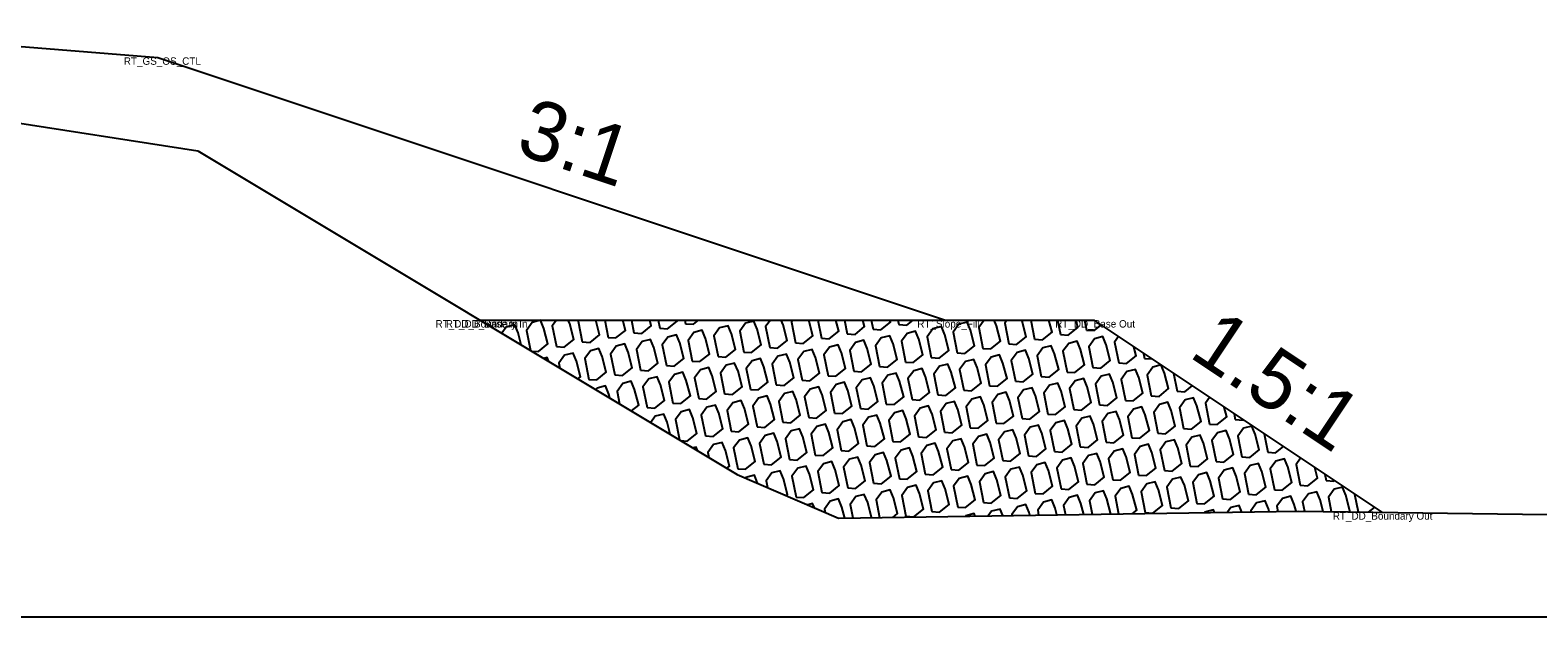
# Model space of a CAD drawing. Extents: x -26 to 203, y -10 to 20020.
# Drawn here: x 118.28 to 138.62, y 15500 to 15507.91 of the extents above; entities that cross this region are included whole.
import ezdxf

# ---------------------------------------------------------------- set-up
doc = ezdxf.new("R2010")
doc.units = 0
for name, color, linetype in [('Default', 7, 'Continuous'), ('Exist Cross Section Cell', 7, 'Continuous'), ('Exist XS Ground Line', 7, 'Continuous'), ('Old_Level_1', 7, 'Continuous'), ('Prop CMT Rip Rap Class II', 7, 'Continuous'), ('Prop CMT Slope Grass', 7, 'Continuous'), ('Prop XS Side Slope Text', 7, 'Continuous')]:
    doc.layers.add(name, color=color, linetype=linetype)

msp = doc.modelspace()

# ---------------------------------------------------------------- linework, layer by layer
at = {"layer": 'Exist Cross Section Cell'}
msp.add_line((100, 15500), (200, 15500), dxfattribs=at)
at = {"layer": 'Exist XS Ground Line'}
for p, q in [((116.112, 15506.968), (120.537, 15506.282)), ((120.537, 15506.282), (127.816, 15501.92)), ((127.816, 15501.92), (129.182, 15501.33)), ((129.182, 15501.33), (135.384, 15501.425)), ((135.384, 15501.425), (151.355, 15501.217))]:
    msp.add_line(p, q, dxfattribs=at)
at = {"layer": 'Old_Level_1'}
for p, q in [((124.378, 15503.98), (124.403, 15504)), ((126.028, 15504), (126.074, 15503.767)), ((126.389, 15504), (126.423, 15503.828)), ((126.749, 15504), (126.771, 15503.89)), ((127.11, 15504), (127.12, 15503.951)), ((128.903, 15504), (128.952, 15503.755)), ((129.264, 15504), (129.3, 15503.816)), ((129.625, 15504), (129.649, 15503.877)), ((129.985, 15504), (129.998, 15503.939)), ((131.778, 15504), (131.829, 15503.742)), ((132.139, 15504), (132.178, 15503.804)), ((132.5, 15504), (132.527, 15503.865)), ((133.299, 15503.552), (133.313, 15503.484)), ((133.313, 15503.484), (133.412, 15503.477)), ((133.702, 15503.283), (133.75, 15503.041)), ((134.521, 15502.737), (134.536, 15502.66)), ((134.924, 15502.469), (134.974, 15502.218)), ((135.743, 15501.923), (135.76, 15501.837)), ((136.146, 15501.654), (136.193, 15501.414)), ((136.335, 15501.412), (136.414, 15501.475))]:
    msp.add_line(p, q, dxfattribs=at)
for points in [[(125.044, 15503.581), (125.134, 15503.575), (125.263, 15503.678), (125.209, 15503.889), (125.164, 15503.998), (125.05, 15503.969), (124.973, 15503.862), (125.026, 15503.592)], [(125.376, 15504), (125.321, 15503.924), (125.377, 15503.644)], [(125.377, 15503.644), (125.482, 15503.636), (125.612, 15503.74), (125.557, 15503.95), (125.537, 15504)], [(125.68, 15504), (125.67, 15503.985), (125.725, 15503.705)], [(125.725, 15503.705), (125.831, 15503.698), (125.96, 15503.801), (125.909, 15504)], [(126.074, 15503.767), (126.179, 15503.759), (126.309, 15503.862), (126.273, 15504)], [(126.423, 15503.828), (126.528, 15503.821), (126.657, 15503.924), (126.638, 15504)], [(126.771, 15503.89), (126.877, 15503.882), (127.006, 15503.985), (127.002, 15504)], [(127.12, 15503.951), (127.225, 15503.944), (127.296, 15504)], [(128.263, 15504), (128.199, 15503.912), (128.255, 15503.632)], [(128.255, 15503.632), (128.36, 15503.624), (128.489, 15503.727), (128.435, 15503.938), (128.409, 15504)], [(128.567, 15504), (128.548, 15503.973), (128.603, 15503.693)], [(128.603, 15503.693), (128.708, 15503.685), (128.838, 15503.789), (128.784, 15503.999), (128.783, 15504)], [(128.952, 15503.755), (129.057, 15503.747), (129.187, 15503.85), (129.148, 15504)], [(129.3, 15503.816), (129.406, 15503.808), (129.535, 15503.912), (129.512, 15504)], [(129.649, 15503.877), (129.754, 15503.87), (129.884, 15503.973), (129.877, 15504)], [(129.998, 15503.939), (130.103, 15503.931), (130.189, 15504)], [(130.352, 15504), (130.451, 15503.993), (130.46, 15504)], [(131.15, 15504), (131.077, 15503.899), (131.132, 15503.619)], [(131.132, 15503.619), (131.237, 15503.612), (131.367, 15503.715), (131.313, 15503.925), (131.282, 15504)], [(131.454, 15504), (131.425, 15503.961), (131.481, 15503.681)], [(131.481, 15503.681), (131.586, 15503.673), (131.716, 15503.776), (131.661, 15503.987), (131.656, 15504)], [(131.829, 15503.742), (131.935, 15503.735), (132.064, 15503.838), (132.022, 15504)], [(132.178, 15503.804), (132.283, 15503.796), (132.413, 15503.899), (132.387, 15504)], [(124.902, 15503.667), (124.86, 15503.827), (124.815, 15503.937), (124.701, 15503.907), (124.64, 15503.823)], [(132.527, 15503.865), (132.632, 15503.858), (132.727, 15503.933)], [(132.962, 15503.777), (132.908, 15503.703), (132.964, 15503.423)], [(125.667, 15503.208), (125.701, 15503.235), (125.646, 15503.446), (125.601, 15503.556), (125.487, 15503.526), (125.41, 15503.42), (125.423, 15503.354)], [(132.964, 15503.423), (133.069, 15503.415), (133.199, 15503.518), (133.167, 15503.64)], [(125.273, 15503.444), (125.252, 15503.494), (125.208, 15503.483)], [(133.534, 15503.395), (133.423, 15503.366), (133.346, 15503.26), (133.402, 15502.98)], [(133.402, 15502.98), (133.507, 15502.972), (133.636, 15503.076), (133.582, 15503.286), (133.538, 15503.393)], [(126.388, 15502.776), (126.487, 15502.854), (126.432, 15503.065), (126.387, 15503.175), (126.273, 15503.145), (126.196, 15503.039), (126.23, 15502.871)], [(126.097, 15502.95), (126.084, 15503.003), (126.038, 15503.113), (125.925, 15503.084), (125.91, 15503.063)], [(133.75, 15503.041), (133.855, 15503.034), (133.956, 15503.114)], [(133.839, 15502.537), (133.944, 15502.53), (134.074, 15502.633), (134.019, 15502.843), (133.974, 15502.953), (133.86, 15502.924), (133.783, 15502.817), (133.839, 15502.537)], [(134.19, 15502.958), (134.132, 15502.879), (134.188, 15502.599)], [(126.911, 15502.463), (126.87, 15502.622), (126.825, 15502.732), (126.711, 15502.703), (126.65, 15502.619)], [(127.055, 15502.376), (127.143, 15502.37), (127.273, 15502.473), (127.218, 15502.684), (127.173, 15502.793), (127.059, 15502.764), (126.982, 15502.658), (127.036, 15502.388)], [(134.188, 15502.599), (134.293, 15502.591), (134.422, 15502.694), (134.388, 15502.826)], [(134.536, 15502.66), (134.641, 15502.653), (134.644, 15502.655)], [(127.677, 15502.004), (127.71, 15502.031), (127.656, 15502.241), (127.611, 15502.351), (127.497, 15502.321), (127.42, 15502.215), (127.433, 15502.15)], [(134.277, 15502.095), (134.382, 15502.087), (134.511, 15502.19), (134.457, 15502.401), (134.412, 15502.511), (134.298, 15502.481), (134.221, 15502.375), (134.277, 15502.095)], [(127.282, 15502.24), (127.262, 15502.289), (127.219, 15502.278)], [(134.974, 15502.218), (135.079, 15502.21), (135.185, 15502.295)], [(135.063, 15501.714), (135.168, 15501.706), (135.297, 15501.809), (135.243, 15502.02), (135.198, 15502.129), (135.084, 15502.1), (135.007, 15501.994), (135.063, 15501.714)], [(135.417, 15502.14), (135.356, 15502.055), (135.411, 15501.775)], [(128.092, 15501.801), (128.048, 15501.908), (127.934, 15501.879), (127.929, 15501.871)], [(128.478, 15501.635), (128.496, 15501.649), (128.442, 15501.86), (128.397, 15501.97), (128.283, 15501.94), (128.206, 15501.834), (128.224, 15501.744)], [(134.714, 15501.652), (134.819, 15501.645), (134.949, 15501.748), (134.894, 15501.958), (134.849, 15502.068), (134.735, 15502.039), (134.658, 15501.932), (134.714, 15501.652)], [(135.411, 15501.775), (135.516, 15501.767), (135.646, 15501.871), (135.61, 15502.012)], [(129.917, 15501.341), (129.98, 15501.391), (129.925, 15501.602), (129.88, 15501.712), (129.766, 15501.682), (129.689, 15501.576), (129.736, 15501.339)], [(130.093, 15501.357), (130.199, 15501.35), (130.328, 15501.453), (130.274, 15501.663), (130.229, 15501.773), (130.115, 15501.744), (130.038, 15501.637), (130.093, 15501.357)], [(130.442, 15501.419), (130.547, 15501.411), (130.677, 15501.514), (130.622, 15501.725), (130.577, 15501.834), (130.463, 15501.805), (130.386, 15501.699), (130.442, 15501.419)], [(130.791, 15501.48), (130.896, 15501.472), (131.025, 15501.576), (130.971, 15501.786), (130.926, 15501.896), (130.812, 15501.867), (130.735, 15501.76), (130.791, 15501.48)], [(133.143, 15501.39), (133.206, 15501.44), (133.151, 15501.651), (133.106, 15501.761), (132.992, 15501.731), (132.915, 15501.625), (132.962, 15501.388)], [(133.32, 15501.406), (133.425, 15501.399), (133.554, 15501.502), (133.5, 15501.712), (133.455, 15501.822), (133.341, 15501.793), (133.264, 15501.686), (133.32, 15501.406)], [(135.76, 15501.837), (135.865, 15501.829), (135.873, 15501.836)], [(136.068, 15501.416), (136.083, 15501.428), (136.029, 15501.639), (135.984, 15501.748), (135.87, 15501.719), (135.793, 15501.612), (135.831, 15501.419)], [(128.858, 15501.47), (128.834, 15501.527), (128.767, 15501.51)], [(129.266, 15501.331), (129.228, 15501.479), (129.183, 15501.589), (129.069, 15501.559), (128.992, 15501.453), (129.001, 15501.408)], [(129.629, 15501.337), (129.577, 15501.54), (129.531, 15501.65), (129.418, 15501.621), (129.341, 15501.514), (129.377, 15501.333)], [(131.766, 15501.369), (131.757, 15501.405), (131.712, 15501.515), (131.598, 15501.485), (131.521, 15501.379), (131.524, 15501.366)], [(132.129, 15501.375), (132.106, 15501.467), (132.06, 15501.576), (131.947, 15501.547), (131.87, 15501.44), (131.883, 15501.371)], [(132.492, 15501.381), (132.454, 15501.528), (132.409, 15501.638), (132.295, 15501.608), (132.218, 15501.502), (132.243, 15501.377)], [(132.855, 15501.386), (132.803, 15501.589), (132.758, 15501.699), (132.644, 15501.67), (132.567, 15501.563), (132.603, 15501.382)], [(134.626, 15501.413), (134.589, 15501.502), (134.476, 15501.473), (134.43, 15501.41)], [(134.992, 15501.419), (134.983, 15501.454), (134.938, 15501.564), (134.824, 15501.535), (134.747, 15501.428), (134.75, 15501.415)], [(135.355, 15501.424), (135.332, 15501.516), (135.287, 15501.625), (135.173, 15501.596), (135.096, 15501.49), (135.11, 15501.42)], [(135.721, 15501.42), (135.68, 15501.577), (135.635, 15501.687), (135.522, 15501.657), (135.444, 15501.551), (135.47, 15501.424)], [(131.028, 15501.358), (131.015, 15501.392), (130.901, 15501.362), (130.896, 15501.356)], [(131.4, 15501.364), (131.363, 15501.453), (131.249, 15501.424), (131.204, 15501.361)], [(134.255, 15501.407), (134.241, 15501.441), (134.127, 15501.412), (134.123, 15501.405)]]:
    msp.add_lwpolyline(points, dxfattribs=at)
for points in [[(127.906, 15503.57), (128.011, 15503.563), (128.141, 15503.666), (128.086, 15503.876), (128.041, 15503.986), (127.927, 15503.957), (127.85, 15503.85)], [(130.784, 15503.558), (130.889, 15503.55), (131.018, 15503.653), (130.964, 15503.864), (130.919, 15503.974), (130.805, 15503.944), (130.728, 15503.838)], [(126.512, 15503.324), (126.617, 15503.317), (126.746, 15503.42), (126.692, 15503.63), (126.647, 15503.74), (126.533, 15503.711), (126.456, 15503.604)], [(126.86, 15503.386), (126.965, 15503.378), (127.095, 15503.481), (127.041, 15503.692), (126.995, 15503.802), (126.882, 15503.772), (126.805, 15503.666)], [(127.209, 15503.447), (127.314, 15503.44), (127.444, 15503.543), (127.389, 15503.753), (127.344, 15503.863), (127.23, 15503.834), (127.153, 15503.727)], [(127.557, 15503.509), (127.663, 15503.501), (127.792, 15503.604), (127.738, 15503.815), (127.693, 15503.925), (127.579, 15503.895), (127.502, 15503.789)], [(129.738, 15503.373), (129.843, 15503.366), (129.973, 15503.469), (129.918, 15503.68), (129.873, 15503.789), (129.759, 15503.76), (129.682, 15503.653)], [(130.086, 15503.435), (130.192, 15503.427), (130.321, 15503.53), (130.267, 15503.741), (130.222, 15503.851), (130.108, 15503.821), (130.031, 15503.715)], [(130.435, 15503.496), (130.54, 15503.489), (130.67, 15503.592), (130.615, 15503.803), (130.57, 15503.912), (130.456, 15503.883), (130.379, 15503.776)], [(132.615, 15503.361), (132.721, 15503.353), (132.85, 15503.457), (132.796, 15503.667), (132.751, 15503.777), (132.637, 15503.748), (132.56, 15503.641)], [(125.814, 15503.201), (125.92, 15503.194), (126.049, 15503.297), (125.995, 15503.508), (125.95, 15503.617), (125.836, 15503.588), (125.759, 15503.481)], [(126.163, 15503.263), (126.268, 15503.255), (126.398, 15503.358), (126.343, 15503.569), (126.298, 15503.679), (126.184, 15503.649), (126.107, 15503.543)], [(128.343, 15503.128), (128.449, 15503.12), (128.578, 15503.223), (128.524, 15503.434), (128.479, 15503.543), (128.365, 15503.514), (128.288, 15503.408)], [(128.692, 15503.189), (128.797, 15503.181), (128.927, 15503.285), (128.872, 15503.495), (128.827, 15503.605), (128.713, 15503.575), (128.636, 15503.469)], [(129.041, 15503.25), (129.146, 15503.243), (129.275, 15503.346), (129.221, 15503.557), (129.176, 15503.666), (129.062, 15503.637), (128.985, 15503.53)], [(129.389, 15503.312), (129.494, 15503.304), (129.624, 15503.408), (129.57, 15503.618), (129.524, 15503.728), (129.411, 15503.698), (129.334, 15503.592)], [(131.57, 15503.177), (131.675, 15503.169), (131.804, 15503.272), (131.75, 15503.483), (131.705, 15503.593), (131.591, 15503.563), (131.514, 15503.457)], [(131.918, 15503.238), (132.024, 15503.231), (132.153, 15503.334), (132.099, 15503.544), (132.053, 15503.654), (131.94, 15503.625), (131.863, 15503.518)], [(132.267, 15503.3), (132.372, 15503.292), (132.502, 15503.395), (132.447, 15503.606), (132.402, 15503.715), (132.288, 15503.686), (132.211, 15503.58)], [(127.298, 15502.943), (127.403, 15502.936), (127.532, 15503.039), (127.478, 15503.249), (127.433, 15503.359), (127.319, 15503.33), (127.242, 15503.223)], [(127.646, 15503.005), (127.752, 15502.997), (127.881, 15503.1), (127.827, 15503.311), (127.781, 15503.42), (127.668, 15503.391), (127.591, 15503.285)], [(127.995, 15503.066), (128.1, 15503.058), (128.23, 15503.162), (128.175, 15503.372), (128.13, 15503.482), (128.016, 15503.453), (127.939, 15503.346)], [(130.175, 15502.931), (130.281, 15502.923), (130.41, 15503.026), (130.356, 15503.237), (130.311, 15503.347), (130.197, 15503.317), (130.12, 15503.211)], [(130.524, 15502.992), (130.629, 15502.985), (130.759, 15503.088), (130.704, 15503.298), (130.659, 15503.408), (130.545, 15503.379), (130.468, 15503.272)], [(130.872, 15503.054), (130.978, 15503.046), (131.107, 15503.149), (131.053, 15503.36), (131.008, 15503.47), (130.894, 15503.44), (130.817, 15503.334)], [(131.221, 15503.115), (131.326, 15503.108), (131.456, 15503.211), (131.401, 15503.421), (131.356, 15503.531), (131.243, 15503.502), (131.165, 15503.395)], [(133.053, 15502.918), (133.158, 15502.911), (133.288, 15503.014), (133.233, 15503.225), (133.188, 15503.334), (133.074, 15503.305), (132.997, 15503.198)], [(126.6, 15502.82), (126.706, 15502.813), (126.835, 15502.916), (126.781, 15503.126), (126.736, 15503.236), (126.622, 15503.207), (126.545, 15503.1)], [(126.949, 15502.882), (127.054, 15502.874), (127.184, 15502.977), (127.129, 15503.188), (127.084, 15503.298), (126.971, 15503.268), (126.893, 15503.162)], [(129.13, 15502.746), (129.235, 15502.739), (129.364, 15502.842), (129.31, 15503.053), (129.265, 15503.162), (129.151, 15503.133), (129.074, 15503.026)], [(129.478, 15502.808), (129.583, 15502.8), (129.713, 15502.903), (129.658, 15503.114), (129.613, 15503.224), (129.5, 15503.194), (129.422, 15503.088)], [(129.827, 15502.869), (129.932, 15502.862), (130.062, 15502.965), (130.007, 15503.176), (129.962, 15503.285), (129.848, 15503.256), (129.771, 15503.149)], [(132.007, 15502.734), (132.112, 15502.726), (132.242, 15502.83), (132.188, 15503.04), (132.142, 15503.15), (132.029, 15503.121), (131.952, 15503.014)], [(132.356, 15502.796), (132.461, 15502.788), (132.591, 15502.891), (132.536, 15503.102), (132.491, 15503.211), (132.377, 15503.182), (132.3, 15503.076)], [(132.704, 15502.857), (132.81, 15502.849), (132.939, 15502.953), (132.885, 15503.163), (132.84, 15503.273), (132.726, 15503.243), (132.649, 15503.137)], [(128.084, 15502.562), (128.189, 15502.554), (128.319, 15502.658), (128.264, 15502.868), (128.219, 15502.978), (128.105, 15502.948), (128.028, 15502.842)], [(128.432, 15502.623), (128.538, 15502.616), (128.667, 15502.719), (128.613, 15502.93), (128.568, 15503.039), (128.454, 15503.01), (128.377, 15502.903)], [(128.781, 15502.685), (128.886, 15502.677), (129.016, 15502.781), (128.961, 15502.991), (128.916, 15503.101), (128.802, 15503.071), (128.725, 15502.965)], [(130.961, 15502.55), (131.067, 15502.542), (131.196, 15502.645), (131.142, 15502.856), (131.097, 15502.966), (130.983, 15502.936), (130.906, 15502.83)], [(131.31, 15502.611), (131.415, 15502.604), (131.545, 15502.707), (131.49, 15502.917), (131.445, 15503.027), (131.331, 15502.998), (131.254, 15502.891)], [(131.659, 15502.673), (131.764, 15502.665), (131.893, 15502.768), (131.839, 15502.979), (131.794, 15503.088), (131.68, 15503.059), (131.603, 15502.953)], [(127.387, 15502.439), (127.492, 15502.431), (127.621, 15502.535), (127.567, 15502.745), (127.522, 15502.855), (127.408, 15502.826), (127.331, 15502.719)], [(127.735, 15502.501), (127.84, 15502.493), (127.97, 15502.596), (127.915, 15502.807), (127.87, 15502.916), (127.757, 15502.887), (127.68, 15502.781)], [(129.567, 15502.304), (129.672, 15502.296), (129.802, 15502.399), (129.747, 15502.61), (129.702, 15502.72), (129.588, 15502.69), (129.511, 15502.584)], [(129.916, 15502.365), (130.021, 15502.358), (130.15, 15502.461), (130.096, 15502.671), (130.051, 15502.781), (129.937, 15502.752), (129.86, 15502.645)], [(130.264, 15502.427), (130.369, 15502.419), (130.499, 15502.522), (130.445, 15502.733), (130.399, 15502.843), (130.286, 15502.813), (130.209, 15502.707)], [(130.613, 15502.488), (130.718, 15502.481), (130.848, 15502.584), (130.793, 15502.794), (130.748, 15502.904), (130.634, 15502.875), (130.557, 15502.768)], [(132.793, 15502.353), (132.899, 15502.345), (133.028, 15502.449), (132.974, 15502.659), (132.928, 15502.769), (132.815, 15502.739), (132.738, 15502.633)], [(133.142, 15502.414), (133.247, 15502.407), (133.377, 15502.51), (133.322, 15502.721), (133.277, 15502.83), (133.163, 15502.801), (133.086, 15502.694)], [(133.49, 15502.476), (133.596, 15502.468), (133.725, 15502.571), (133.671, 15502.782), (133.626, 15502.892), (133.512, 15502.862), (133.435, 15502.756)], [(128.521, 15502.119), (128.626, 15502.112), (128.756, 15502.215), (128.702, 15502.426), (128.656, 15502.535), (128.543, 15502.506), (128.466, 15502.399)], [(128.87, 15502.181), (128.975, 15502.173), (129.105, 15502.276), (129.05, 15502.487), (129.005, 15502.597), (128.891, 15502.567), (128.814, 15502.461)], [(129.218, 15502.242), (129.324, 15502.235), (129.453, 15502.338), (129.399, 15502.548), (129.354, 15502.658), (129.24, 15502.629), (129.163, 15502.522)], [(131.399, 15502.107), (131.504, 15502.099), (131.634, 15502.203), (131.579, 15502.413), (131.534, 15502.523), (131.42, 15502.494), (131.343, 15502.387)], [(131.747, 15502.169), (131.853, 15502.161), (131.982, 15502.264), (131.928, 15502.475), (131.883, 15502.584), (131.769, 15502.555), (131.692, 15502.449)], [(132.096, 15502.23), (132.201, 15502.222), (132.331, 15502.326), (132.276, 15502.536), (132.231, 15502.646), (132.117, 15502.616), (132.04, 15502.51)], [(132.445, 15502.291), (132.55, 15502.284), (132.679, 15502.387), (132.625, 15502.598), (132.58, 15502.707), (132.466, 15502.678), (132.389, 15502.571)], [(134.625, 15502.156), (134.73, 15502.149), (134.86, 15502.252), (134.805, 15502.462), (134.76, 15502.572), (134.647, 15502.543), (134.569, 15502.436)], [(127.824, 15501.996), (127.929, 15501.989), (128.059, 15502.092), (128.004, 15502.303), (127.959, 15502.412), (127.845, 15502.383), (127.768, 15502.276)], [(128.173, 15502.058), (128.278, 15502.05), (128.407, 15502.154), (128.353, 15502.364), (128.308, 15502.474), (128.194, 15502.444), (128.117, 15502.338)], [(130.353, 15501.923), (130.458, 15501.915), (130.588, 15502.018), (130.533, 15502.229), (130.488, 15502.339), (130.375, 15502.309), (130.297, 15502.203)], [(130.702, 15501.984), (130.807, 15501.977), (130.936, 15502.08), (130.882, 15502.29), (130.837, 15502.4), (130.723, 15502.371), (130.646, 15502.264)], [(131.05, 15502.046), (131.156, 15502.038), (131.285, 15502.141), (131.231, 15502.352), (131.185, 15502.461), (131.072, 15502.432), (130.995, 15502.326)], [(133.231, 15501.91), (133.336, 15501.903), (133.466, 15502.006), (133.411, 15502.216), (133.366, 15502.326), (133.252, 15502.297), (133.175, 15502.19)], [(133.579, 15501.972), (133.685, 15501.964), (133.814, 15502.067), (133.76, 15502.278), (133.715, 15502.388), (133.601, 15502.358), (133.524, 15502.252)], [(133.928, 15502.033), (134.033, 15502.026), (134.163, 15502.129), (134.108, 15502.339), (134.063, 15502.449), (133.949, 15502.42), (133.872, 15502.313)], [(129.307, 15501.738), (129.413, 15501.731), (129.542, 15501.834), (129.488, 15502.044), (129.442, 15502.154), (129.329, 15502.125), (129.252, 15502.018)], [(129.656, 15501.8), (129.761, 15501.792), (129.891, 15501.895), (129.836, 15502.106), (129.791, 15502.216), (129.677, 15502.186), (129.6, 15502.08)], [(130.004, 15501.861), (130.11, 15501.854), (130.239, 15501.957), (130.185, 15502.167), (130.14, 15502.277), (130.026, 15502.248), (129.949, 15502.141)], [(132.185, 15501.726), (132.29, 15501.718), (132.42, 15501.822), (132.365, 15502.032), (132.32, 15502.142), (132.206, 15502.112), (132.129, 15502.006)], [(132.534, 15501.787), (132.639, 15501.78), (132.768, 15501.883), (132.714, 15502.094), (132.669, 15502.203), (132.555, 15502.174), (132.478, 15502.067)], [(132.882, 15501.849), (132.987, 15501.841), (133.117, 15501.944), (133.062, 15502.155), (133.017, 15502.265), (132.904, 15502.235), (132.827, 15502.129)], [(128.61, 15501.615), (128.715, 15501.608), (128.845, 15501.711), (128.79, 15501.921), (128.745, 15502.031), (128.632, 15502.002), (128.554, 15501.895)], [(128.959, 15501.677), (129.064, 15501.669), (129.193, 15501.772), (129.139, 15501.983), (129.094, 15502.093), (128.98, 15502.063), (128.903, 15501.957)], [(131.139, 15501.542), (131.244, 15501.534), (131.374, 15501.637), (131.319, 15501.848), (131.274, 15501.957), (131.161, 15501.928), (131.084, 15501.822)], [(131.488, 15501.603), (131.593, 15501.595), (131.723, 15501.699), (131.668, 15501.909), (131.623, 15502.019), (131.509, 15501.989), (131.432, 15501.883)], [(131.836, 15501.664), (131.942, 15501.657), (132.071, 15501.76), (132.017, 15501.971), (131.972, 15502.08), (131.858, 15502.051), (131.781, 15501.944)], [(134.017, 15501.529), (134.122, 15501.522), (134.252, 15501.625), (134.197, 15501.835), (134.152, 15501.945), (134.038, 15501.916), (133.961, 15501.809)], [(134.365, 15501.591), (134.471, 15501.583), (134.6, 15501.686), (134.546, 15501.897), (134.501, 15502.007), (134.387, 15501.977), (134.31, 15501.871)], [(133.668, 15501.468), (133.773, 15501.46), (133.903, 15501.563), (133.849, 15501.774), (133.803, 15501.884), (133.69, 15501.854), (133.613, 15501.748)]]:
    msp.add_lwpolyline(points, close=True, dxfattribs=at)
at = {"layer": 'Prop CMT Rip Rap Class II'}
for points in [[(124.345, 15504), (124.345, 15504)], [(124.345, 15504), (132.627, 15504), (136.512, 15501.41)]]:
    msp.add_lwpolyline(points, dxfattribs=at)
at = {"layer": 'Prop CMT Slope Grass'}
for points in [[(115.417, 15507.909), (120, 15507.542)], [(120, 15507.542), (130.627, 15504)]]:
    msp.add_lwpolyline(points, dxfattribs=at)

# ---------------------------------------------------------------- texts
at = {"layer": 'Default'}
for s, p in [('RT_GS_OS_CTL', (119.54, 15507.442)), ('RT_DD_Boundary In', (123.745, 15503.9)), ('RT_DD_Base In', (123.884, 15503.9)), ('RT_Slope_Fill', (130.245, 15503.9)), ('RT_DD_Base Out', (132.105, 15503.9)), ('RT_DD_Boundary Out', (135.851, 15501.31))]:
    msp.add_text(s, height=0.1, dxfattribs=at).set_placement(p)
at = {"layer": 'Prop XS Side Slope Text'}
for s, rotation, p in [('3:1', 341.5668, (124.807, 15506.256)), ('1.5:1', 326.3086, (133.893, 15503.516))]:
    msp.add_text(s, height=0.8, rotation=rotation, dxfattribs=at).set_placement(p)

doc.saveas('drawing.dxf')
